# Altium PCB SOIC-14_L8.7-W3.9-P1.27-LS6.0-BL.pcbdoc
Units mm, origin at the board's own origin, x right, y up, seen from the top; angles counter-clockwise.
Board outline 21.78 x 19.98 mm, 2 copper layers (Top Layer, Bottom Layer), stack 0 mm thick; 1 components, 0 nets, 14 pads, 0 vias.
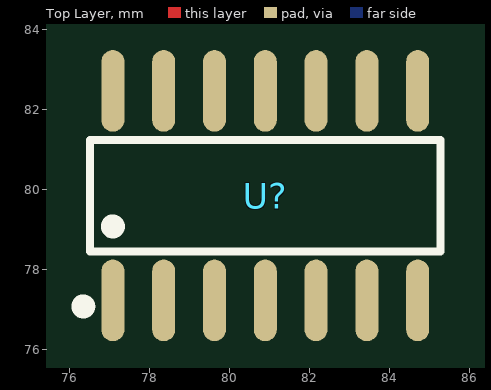
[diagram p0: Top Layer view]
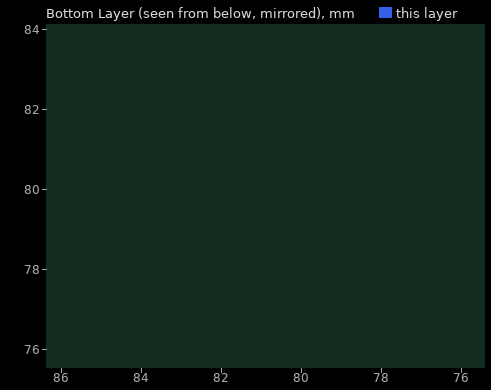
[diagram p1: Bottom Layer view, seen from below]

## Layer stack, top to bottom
Top Layer: signal copper (thickness not stored)
Bottom Layer: signal copper (thickness not stored)

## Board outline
91.631,69.85 69.85,69.85 69.85,89.826 91.631,89.826

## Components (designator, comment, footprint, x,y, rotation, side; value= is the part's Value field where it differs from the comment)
U? "" SOIC-14_L8.7-W3.9-P1.27-LS6.0-BL 80.9,79.838 r0 top

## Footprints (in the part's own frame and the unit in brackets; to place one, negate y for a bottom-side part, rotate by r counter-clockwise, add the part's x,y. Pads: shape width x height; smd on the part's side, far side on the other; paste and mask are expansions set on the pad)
SOIC-14_L8.7-W3.9-P1.27-LS6.0-BL [mm]
  oval 0.574x2.038 smd: 1(-3.81,-2.619) 2(-2.54,-2.619) 3(-1.27,-2.619) 4(0,-2.619) 5(1.27,-2.619) 6(2.54,-2.619) 7(3.81,-2.619) 8(3.81,2.619) 9(2.54,2.619) 10(1.27,2.619) 11(0,2.619) 12(-1.27,2.619) 13(-2.54,2.619) 14(-3.81,2.619)
  silkscreen extent -4.7,-2.92 4.38,1.4

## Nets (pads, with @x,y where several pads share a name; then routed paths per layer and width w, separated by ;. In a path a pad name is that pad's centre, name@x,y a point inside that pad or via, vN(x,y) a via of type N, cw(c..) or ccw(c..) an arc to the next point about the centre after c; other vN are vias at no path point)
pads on no net: U?.1 U?.2 U?.3 U?.4 U?.5 U?.6 U?.7 U?.8 U?.9 U?.10 U?.11 U?.12 U?.13 U?.14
